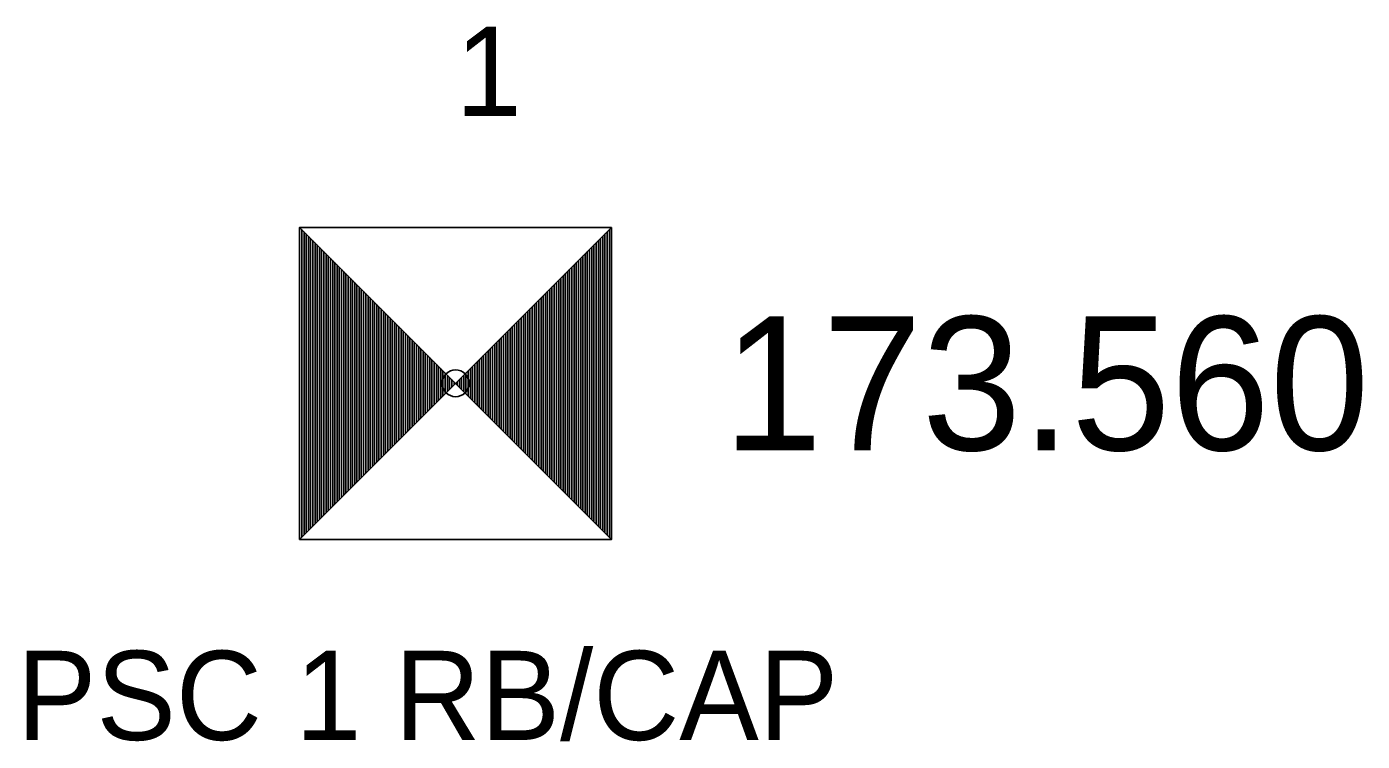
# Model space of a CAD drawing. Extents: x 2449052 to 2452984, y 1012343 to 1015262.
# Drawn here: x 2449051.91 to 2449066.89, y 1012565.25 to 1012573.26 of the extents above; entities that cross this region are included whole.
import ezdxf

# ---------------------------------------------------------------- set-up
doc = ezdxf.new("R2010")
doc.units = 0
for name, color, linetype in [('RD_HC_Survey', 7, 'Continuous'), ('RD_HC_Survey_ELEV', 7, 'Continuous'), ('RD_HC_txCode', 7, 'Continuous'), ('RD_SMD_Locator', 7, 'Continuous')]:
    doc.layers.add(name, color=color, linetype=linetype)

msp = doc.modelspace()

# ---------------------------------------------------------------- linework, layer by layer
at = {"layer": 'RD_HC_Survey'}
for p, q in [((2449054.973, 1012571.011), (2449058.472, 1012567.512)), ((2449058.472, 1012571.011), (2449054.973, 1012567.512)), ((2449054.997, 1012570.987), (2449054.997, 1012567.536)), ((2449058.448, 1012570.987), (2449058.448, 1012567.536)), ((2449055.022, 1012570.962), (2449055.022, 1012567.561)), ((2449055.047, 1012570.937), (2449055.047, 1012567.586)), ((2449055.072, 1012570.912), (2449055.072, 1012567.611)), ((2449055.096, 1012570.888), (2449055.096, 1012567.635)), ((2449055.121, 1012570.863), (2449055.121, 1012567.66)), ((2449055.146, 1012570.838), (2449055.146, 1012567.685)), ((2449058.299, 1012570.838), (2449058.299, 1012567.685)), ((2449058.324, 1012570.863), (2449058.324, 1012567.66)), ((2449058.349, 1012570.888), (2449058.349, 1012567.635)), ((2449058.373, 1012570.912), (2449058.373, 1012567.611)), ((2449058.398, 1012570.937), (2449058.398, 1012567.586)), ((2449058.423, 1012570.962), (2449058.423, 1012567.561)), ((2449055.17, 1012570.814), (2449055.17, 1012567.709)), ((2449055.195, 1012570.789), (2449055.195, 1012567.734)), ((2449055.22, 1012570.764), (2449055.22, 1012567.759)), ((2449055.245, 1012570.739), (2449055.245, 1012567.784)), ((2449055.269, 1012570.715), (2449055.269, 1012567.808)), ((2449055.294, 1012570.69), (2449055.294, 1012567.833)), ((2449058.151, 1012570.69), (2449058.151, 1012567.833)), ((2449058.176, 1012570.715), (2449058.176, 1012567.808)), ((2449058.2, 1012570.739), (2449058.2, 1012567.784)), ((2449058.225, 1012570.764), (2449058.225, 1012567.759)), ((2449058.25, 1012570.789), (2449058.25, 1012567.734)), ((2449058.275, 1012570.814), (2449058.275, 1012567.709)), ((2449055.319, 1012570.665), (2449055.319, 1012567.858)), ((2449055.344, 1012570.64), (2449055.344, 1012567.883)), ((2449055.368, 1012570.616), (2449055.368, 1012567.907)), ((2449055.393, 1012570.591), (2449055.393, 1012567.932)), ((2449055.418, 1012570.566), (2449055.418, 1012567.957)), ((2449055.443, 1012570.541), (2449055.443, 1012567.982)), ((2449055.467, 1012570.517), (2449055.467, 1012568.006)), ((2449057.978, 1012570.517), (2449057.978, 1012568.006)), ((2449058.002, 1012570.541), (2449058.002, 1012567.982)), ((2449058.027, 1012570.566), (2449058.027, 1012567.957)), ((2449058.052, 1012570.591), (2449058.052, 1012567.932)), ((2449058.077, 1012570.616), (2449058.077, 1012567.907)), ((2449058.101, 1012570.64), (2449058.101, 1012567.883)), ((2449058.126, 1012570.665), (2449058.126, 1012567.858)), ((2449055.492, 1012570.492), (2449055.492, 1012568.031)), ((2449055.517, 1012570.467), (2449055.517, 1012568.056)), ((2449055.542, 1012570.442), (2449055.542, 1012568.081)), ((2449055.566, 1012570.418), (2449055.566, 1012568.105)), ((2449055.591, 1012570.393), (2449055.591, 1012568.13)), ((2449055.616, 1012570.368), (2449055.616, 1012568.155)), ((2449057.829, 1012570.368), (2449057.829, 1012568.155)), ((2449057.854, 1012570.393), (2449057.854, 1012568.13)), ((2449057.879, 1012570.418), (2449057.879, 1012568.105)), ((2449057.903, 1012570.442), (2449057.903, 1012568.081)), ((2449057.928, 1012570.467), (2449057.928, 1012568.056)), ((2449057.953, 1012570.492), (2449057.953, 1012568.031)), ((2449055.641, 1012570.343), (2449055.641, 1012568.18)), ((2449055.665, 1012570.319), (2449055.665, 1012568.204)), ((2449055.69, 1012570.294), (2449055.69, 1012568.229)), ((2449055.715, 1012570.269), (2449055.715, 1012568.254)), ((2449055.74, 1012570.244), (2449055.74, 1012568.279)), ((2449055.764, 1012570.22), (2449055.764, 1012568.303)), ((2449057.681, 1012570.22), (2449057.681, 1012568.303)), ((2449057.705, 1012570.244), (2449057.705, 1012568.279)), ((2449057.73, 1012570.269), (2449057.73, 1012568.254)), ((2449057.755, 1012570.294), (2449057.755, 1012568.229)), ((2449057.78, 1012570.319), (2449057.78, 1012568.204)), ((2449057.804, 1012570.343), (2449057.804, 1012568.18)), ((2449055.789, 1012570.195), (2449055.789, 1012568.328)), ((2449055.814, 1012570.17), (2449055.814, 1012568.353)), ((2449055.839, 1012570.145), (2449055.839, 1012568.378)), ((2449055.863, 1012570.121), (2449055.863, 1012568.402)), ((2449055.888, 1012570.096), (2449055.888, 1012568.427)), ((2449055.913, 1012570.071), (2449055.913, 1012568.452)), ((2449057.532, 1012570.071), (2449057.532, 1012568.452)), ((2449057.557, 1012570.096), (2449057.557, 1012568.427)), ((2449057.582, 1012570.121), (2449057.582, 1012568.402)), ((2449057.606, 1012570.145), (2449057.606, 1012568.378)), ((2449057.631, 1012570.17), (2449057.631, 1012568.353)), ((2449057.656, 1012570.195), (2449057.656, 1012568.328)), ((2449055.938, 1012570.046), (2449055.938, 1012568.477)), ((2449055.962, 1012570.022), (2449055.962, 1012568.501)), ((2449055.987, 1012569.997), (2449055.987, 1012568.526)), ((2449056.012, 1012569.972), (2449056.012, 1012568.551)), ((2449056.037, 1012569.947), (2449056.037, 1012568.576)), ((2449056.061, 1012569.923), (2449056.061, 1012568.6)), ((2449057.384, 1012569.923), (2449057.384, 1012568.6)), ((2449057.408, 1012569.947), (2449057.408, 1012568.576)), ((2449057.433, 1012569.972), (2449057.433, 1012568.551)), ((2449057.458, 1012569.997), (2449057.458, 1012568.526)), ((2449057.483, 1012570.022), (2449057.483, 1012568.501)), ((2449057.507, 1012570.046), (2449057.507, 1012568.477)), ((2449056.086, 1012569.898), (2449056.086, 1012568.625)), ((2449056.111, 1012569.873), (2449056.111, 1012568.65)), ((2449056.136, 1012569.848), (2449056.136, 1012568.675)), ((2449056.16, 1012569.824), (2449056.16, 1012568.699)), ((2449056.185, 1012569.799), (2449056.185, 1012568.724)), ((2449056.21, 1012569.774), (2449056.21, 1012568.749)), ((2449057.235, 1012569.774), (2449057.235, 1012568.749)), ((2449057.26, 1012569.799), (2449057.26, 1012568.724)), ((2449057.285, 1012569.824), (2449057.285, 1012568.699)), ((2449057.309, 1012569.848), (2449057.309, 1012568.675)), ((2449057.334, 1012569.873), (2449057.334, 1012568.65)), ((2449057.359, 1012569.898), (2449057.359, 1012568.625)), ((2449056.235, 1012569.749), (2449056.235, 1012568.774)), ((2449056.259, 1012569.725), (2449056.259, 1012568.798)), ((2449056.284, 1012569.7), (2449056.284, 1012568.823)), ((2449056.309, 1012569.675), (2449056.309, 1012568.848)), ((2449056.334, 1012569.65), (2449056.334, 1012568.873)), ((2449056.358, 1012569.626), (2449056.358, 1012568.897)), ((2449057.087, 1012569.626), (2449057.087, 1012568.897)), ((2449057.111, 1012569.65), (2449057.111, 1012568.873)), ((2449057.136, 1012569.675), (2449057.136, 1012568.848)), ((2449057.161, 1012569.7), (2449057.161, 1012568.823)), ((2449057.186, 1012569.725), (2449057.186, 1012568.798)), ((2449057.21, 1012569.749), (2449057.21, 1012568.774)), ((2449056.383, 1012569.601), (2449056.383, 1012568.922)), ((2449056.408, 1012569.576), (2449056.408, 1012568.947)), ((2449056.433, 1012569.551), (2449056.433, 1012568.972)), ((2449056.457, 1012569.527), (2449056.457, 1012568.996)), ((2449056.482, 1012569.502), (2449056.482, 1012569.021)), ((2449056.507, 1012569.477), (2449056.507, 1012569.046)), ((2449056.938, 1012569.477), (2449056.938, 1012569.046)), ((2449056.963, 1012569.502), (2449056.963, 1012569.021)), ((2449056.988, 1012569.527), (2449056.988, 1012568.996)), ((2449057.012, 1012569.551), (2449057.012, 1012568.972)), ((2449057.037, 1012569.576), (2449057.037, 1012568.947)), ((2449057.062, 1012569.601), (2449057.062, 1012568.922)), ((2449056.532, 1012569.452), (2449056.532, 1012569.071)), ((2449056.556, 1012569.428), (2449056.556, 1012569.095)), ((2449056.581, 1012569.403), (2449056.581, 1012569.12)), ((2449056.606, 1012569.378), (2449056.606, 1012569.145)), ((2449056.631, 1012569.353), (2449056.631, 1012569.17)), ((2449056.655, 1012569.329), (2449056.655, 1012569.194)), ((2449056.79, 1012569.329), (2449056.79, 1012569.194)), ((2449056.814, 1012569.353), (2449056.814, 1012569.17)), ((2449056.839, 1012569.378), (2449056.839, 1012569.145)), ((2449056.864, 1012569.403), (2449056.864, 1012569.12)), ((2449056.889, 1012569.428), (2449056.889, 1012569.095)), ((2449056.913, 1012569.452), (2449056.913, 1012569.071)), ((2449056.68, 1012569.304), (2449056.68, 1012569.219)), ((2449056.705, 1012569.279), (2449056.705, 1012569.244)), ((2449056.74, 1012569.279), (2449056.74, 1012569.244)), ((2449056.765, 1012569.304), (2449056.765, 1012569.219))]:
    msp.add_line(p, q, dxfattribs=at)
msp.add_lwpolyline([(2449058.472, 1012571.011), (2449054.973, 1012571.011), (2449054.973, 1012567.512), (2449058.472, 1012567.512)], close=True, dxfattribs=at)
at = {"layer": 'RD_SMD_Locator'}
msp.add_circle((2449056.723, 1012569.262), 0.15, dxfattribs=at)

# ---------------------------------------------------------------- texts
at = {"layer": 'RD_HC_Survey_ELEV'}
msp.add_text('173.560', height=1.5, dxfattribs=at).set_placement((2449059.723, 1012568.512))
at = {"layer": 'RD_HC_txCode'}
for s, p in [('1', (2449056.723, 1012572.262)), ('PSC 1 RB/CAP', (2449051.801, 1012565.262))]:
    msp.add_text(s, height=1, dxfattribs=at).set_placement(p)

doc.saveas('drawing.dxf')
